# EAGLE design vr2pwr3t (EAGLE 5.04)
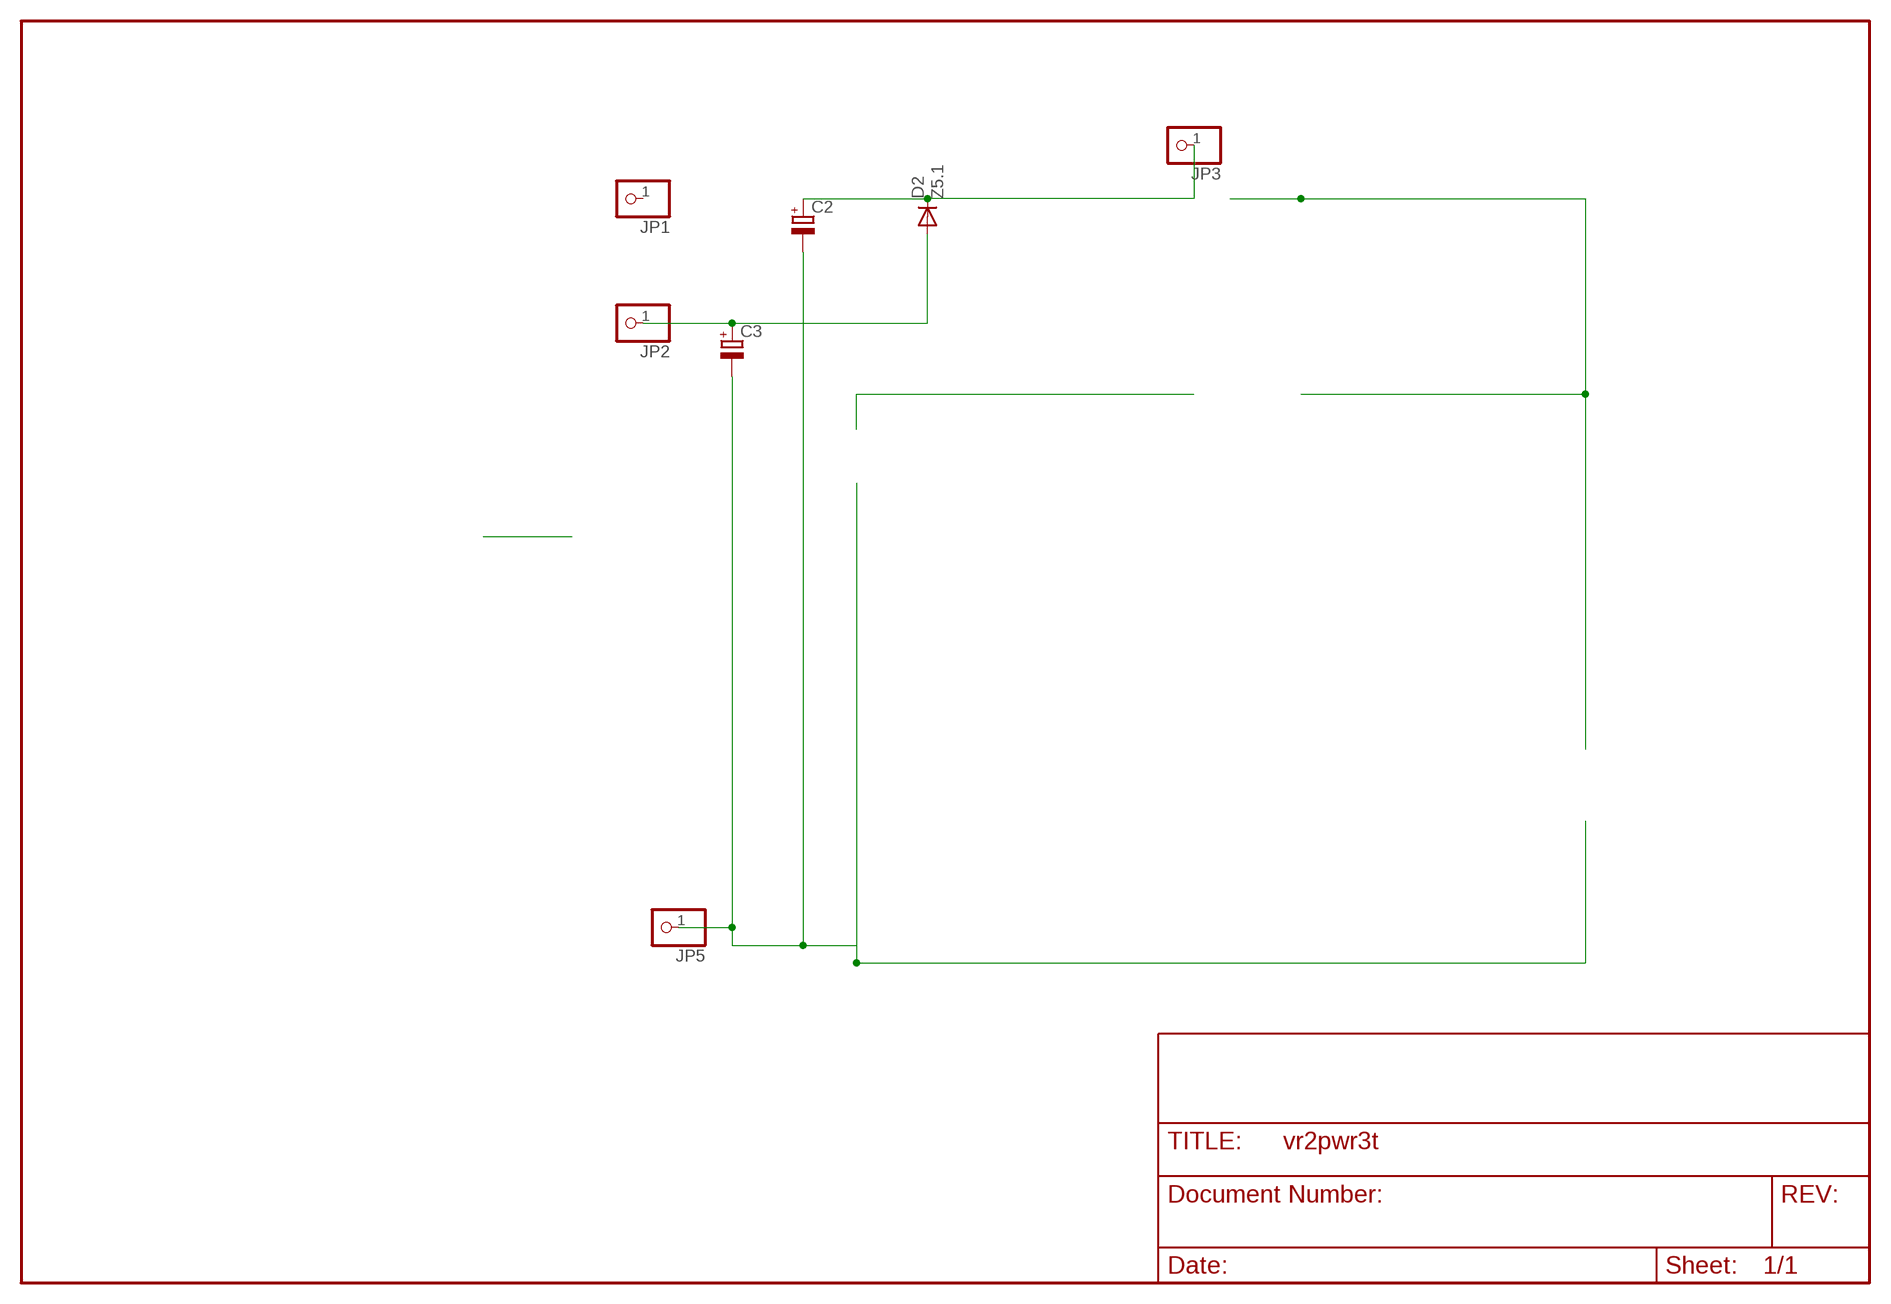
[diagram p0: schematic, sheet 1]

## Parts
C2  CPOL-EUE2.5-7  [E2,5-7]
C3  CPOL-EUE2-4  [E2-4]
D2  Z5.1  DIODE-D-2.5  [D-2.5]
JP1  PINHD-1X1  [1X01]
JP2  PINHD-1X1  [1X01]
JP3  PINHD-1X1  [1X01]
JP5  PINHD-1X1  [1X01]

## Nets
LOAD: C2.+ D2.C JP3.1
N$4: C3.+ D2.A JP2.1
N$30: C2.- C3.- JP5.1
Unconnected: JP1.1

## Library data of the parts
C2 C3 = rcl(2):CPOL-EU: POLARIZED CAPACITOR, European symbol
D2 = diode:DIODE-: DIODE
JP1-JP3 JP5 = pinhead:PINHD-1X1: PIN HEADER

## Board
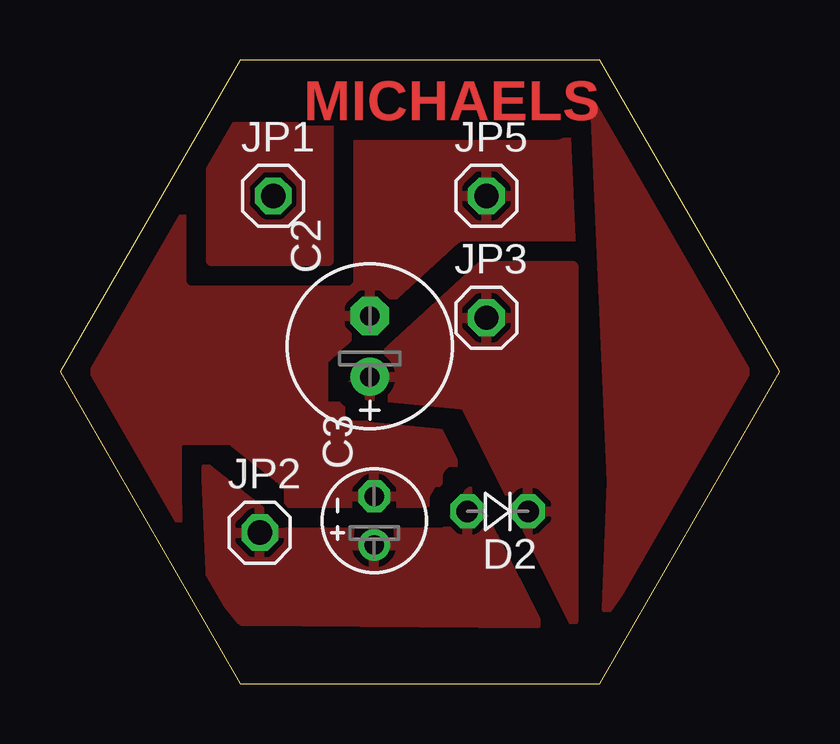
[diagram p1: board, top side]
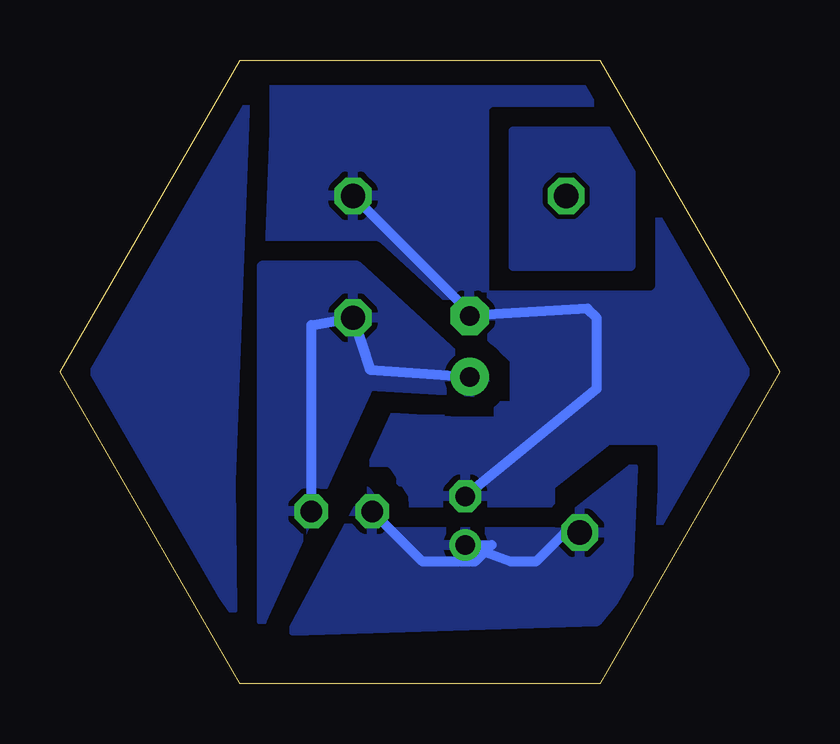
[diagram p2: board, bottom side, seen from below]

Size 30 x 25.98 mm. Coordinates in mm from the lower left corner, seen from the top.
Outline: 7.5,0 22.5,0 30,12.99 22.5,25.98 7.5,25.98 0,12.99 7.5,0
Copper layers (1*16): Top 0.035mm / dielectric 1.5mm / Bottom 0.035mm
Design rules "default": minimum track width 10mil, minimum drill 24mil, track to track 8mil, track to pad 8mil, pad to pad 8mil, via to via 8mil, smd to smd 8mil, copper to edge 40mil, drill to drill 8mil, minimum pad ring 10mil, minimum via ring 8mil, stop-mask expansion 4mil, vias tented up to drill 0mil, thermal gap 10mil

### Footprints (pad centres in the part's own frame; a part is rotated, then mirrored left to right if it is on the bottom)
E2,5-7 = drill 0.813 pad 1.6 round: + -1.27,0 | drill 0.813 pad 1.6 octagon: - 1.27,0
E2-4 = drill 0.813 pad 1.27 round: + -1.016,0 | drill 0.813 pad 1.27 octagon: - 1.016,0
D-2.5 = drill 0.9 octagon: A 1.27,0; C -1.27,0
1X01 = drill 1.016 octagon: 1 0,0

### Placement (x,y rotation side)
C2  12.92,14.05 90 top
C3  13.1,6.78 90 top
D2  18.25,7.18 180 top
JP1  8.89,20.32 0 top
JP2  8.33,6.29 0 top
JP3  17.78,15.24 0 top
JP5  17.78,20.32 0 top

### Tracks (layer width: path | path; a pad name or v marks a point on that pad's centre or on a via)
LOAD
  Bottom 0.406: D2.C 19.52,14.94 JP3.1 17.08,13.08 C2.+
  pour Bottom: 17.6,17.4 21.59,17.4 21.59,2.6 17.1,12.4 11.8,12.1
  pour Top: 17.6,17.4 21.4,17.4 21.4,2.6 16.9,11.6 11.8,12.1
N$1
  pour Top: 8.6,17.6 6.3,17.6 6.3,23.2 11.2,23.2 11.2,17.6
  pour Bottom: 8.5,17.4 6.2,17.4 6.2,23 11.1,23 11.1,17.4
  pour Top (rank 2): 22.8,3.1 23,8.4 22.27,25.5 29.66,13.49 26.4,8.2
  pour Bottom (rank 2): 22.8,3.1 22.86,8.4 22.23,25.5 29.66,13.49 26.4,8.2
N$4
  Bottom 0.406: JP2.1 8.95,6.29 10.16,5.08 11.21,5.08 C3.+ 12,5.78 12.7,5.08 14.88,5.08 D2.A
  pour Bottom: 6.1,9 9.5,6.3 16.1,6.3 17.2,8 20.3,2.2 7.6,2.6 6.3,4.2
  pour Top: 6.1,9 9.5,6.3 16.1,6.3 17.1,8 19.9,2.5 7.6,2.6 6.3,4.2
N$30
  Bottom 0.406: JP5.1 13.08,15.62 C2.- 8,15.62 7.62,15.24 7.62,12.28 C3.-
  pour Bottom (isolate 0.813, rank 3): 7.4,28.4 23.7,28.4 25,27.1 30.5,15.1 22.6,1.7 7.6,1.8 -0.3,14.5 6.3,26.2
  pour Top (isolate 0.813, rank 3): 7.4,28.4 23.7,28.4 25,27.1 30.5,15.1 22.6,1.7 7.6,1.8 -0.3,14.5 6.3,26.2

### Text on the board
Top: MICHAELS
